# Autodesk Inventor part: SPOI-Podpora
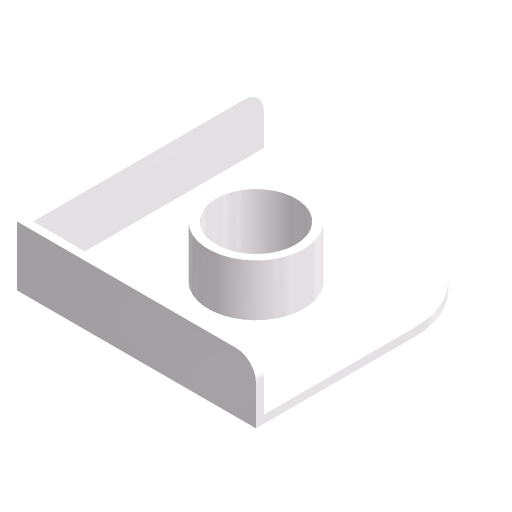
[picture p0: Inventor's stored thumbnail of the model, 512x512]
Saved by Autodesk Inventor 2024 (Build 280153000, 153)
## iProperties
Company: ATC
Shininess: 21.0
Length Units: 11269
Angle Units: 11279
Time Units: 11290
Mass Units: 11283
Length Display Precision: 3
Angle Display Precision: 2
Compacted: True
Created: 2023-03
Part Number: SPOI-Podpora
Document SubType Name: Modeling
Designer: Andrzej Jaskulski
Material: Kurs-AJ
Density: 1 g/cm^3
Mass: 11.2231 g
Surface Area: 118.487 cm^2
Volume: 11.2231 cm^3
Appearance: Kurs-AJ
Checked By: A.J.
Engr Approved By: Andrzej Jaskulski
Mfg Approved By: Andrzej Jaskulski
Authority: A.J.
Density: 0.0
Volumn: 0.0
Area: 0.0
PropertySet Name: Model Information
Control State: 0
Master: False
Checked Out: False
Title: A.J.: Kurs R2024-MEP
Author: Andrzej Jaskulski
Revision Number: 1/24
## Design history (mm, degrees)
sketch "Sketch1"
  geometry: L1 (0, 0)-(60, 0); L2 (60, 0)-(60, 60); L3 (60, 60)-(0, 60); L4 (0, 60)-(0, 0)
  constraints: 8 end point, 2 parallel, 1 horizontal, 1 perpendicular, 1 other
  dimensions: "d0" = 60 distance of L1.start L1.end (= x); "d1" = 60 distance of L1.end L2.end (= y)
extrude "Baza" new body sketch "Sketch1" distance "d2" = 15 (= h); taper "d3" = 0 deg
sketch "Sketch3"
  geometry: L1 (0, 0)-(0, 60) reference; L2 (60, 0)-(0, 0) reference; 1 further point
  dimensions: "d9" = 30 distance from line of L1 point (30, 30) (= Lx); "d10" = 30 distance from line of L2 point (30, 30) (= Ly)
hole "Otwór" sketch "Sketch3" diameter "d7" = 20; stored, may be unused: countersink angle "d18" = 60 deg, drill point angle "d20" = 118 deg; dims "d8" = 6, "d16" = 4, "d17" = 2, "d19" = 8
fillet "Zaokrąglenie1" dims "d4" = 20 (= d)
fillet "Zaokrąglenie2" dims "d5" = 5 (= 0.5 x r)
feature "Skorupa1" dims "d6" = 2
node "Bryła1"
node "Korpusy bryłowe"
node "Korpusy powierzchniowe"
other parameters: "x" = 60 [user parameter; used in 1 equation term], "y" = 60 [user parameter; used in 1 equation term], "h" = 15 [user parameter; used in 1 equation term], "Lx" = 30 [user parameter; used in 1 equation term], "Ly" = 30 [user parameter; used in 1 equation term], "L2" = 1 [user parameter]
